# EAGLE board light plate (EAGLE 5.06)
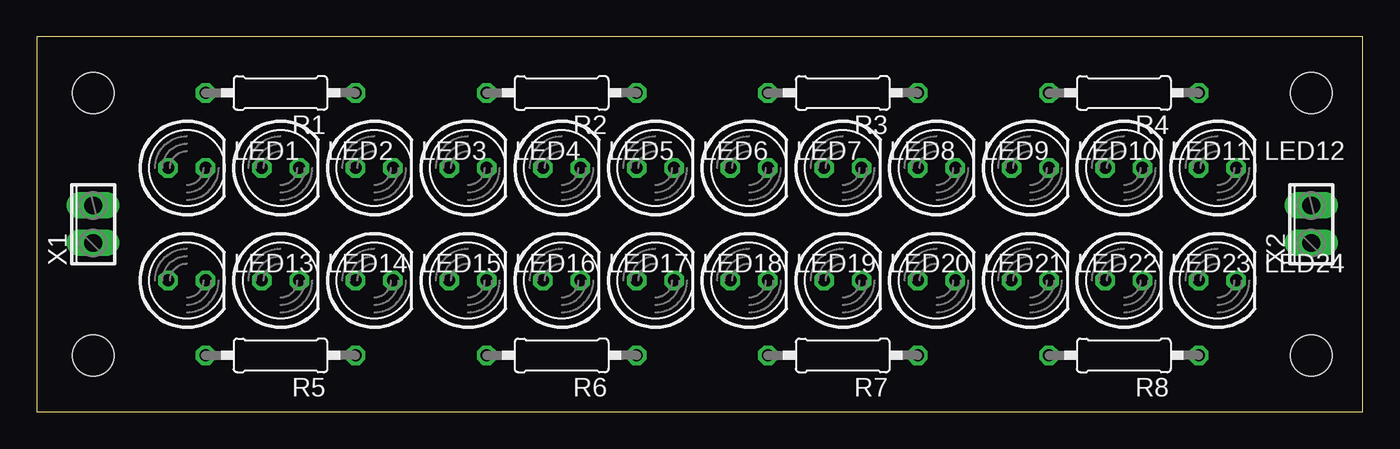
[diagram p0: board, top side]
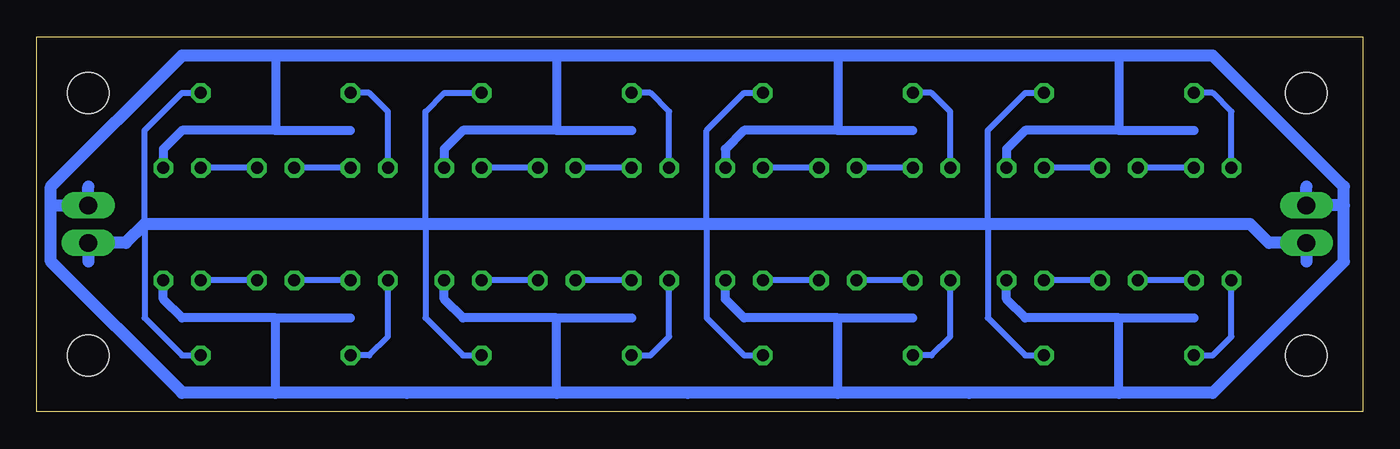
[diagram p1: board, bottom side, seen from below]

Size 89.84 x 25.39 mm. Coordinates in mm from the lower left corner, seen from the top.
Outline: 0,0 89.84,0 89.84,25.39 0,25.39 0,0
Copper layers (1*16): Top 0.035mm / dielectric 1.5mm / Bottom 0.035mm
Design rules "default": minimum track width 10mil, minimum drill 24mil, track to track 8mil, track to pad 8mil, pad to pad 8mil, via to via 8mil, smd to smd 8mil, copper to edge 40mil, drill to drill 8mil, minimum pad ring 10mil, minimum via ring 8mil, stop-mask expansion 4mil, vias tented up to drill 0mil, thermal gap 10mil
Holes 2.8 mm at 3.81,21.59 3.81,3.81 86.36,21.59 86.36,3.81

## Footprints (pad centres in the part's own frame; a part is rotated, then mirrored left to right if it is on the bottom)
LED5MM = drill 0.813 octagon: A -1.27,0; K 1.27,0
0207/10 = drill 0.813 octagon: 1 -5.08,0; 2 5.08,0
2POL254 = drill 1.2 long: 1 -1.27,0; 2 1.27,0

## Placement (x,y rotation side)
LED1  [LED5MM]  10.16,16.51 0 top
LED2  [LED5MM]  16.51,16.51 0 top
LED3  [LED5MM]  22.86,16.51 0 top
LED4  [LED5MM]  29.21,16.51 0 top
LED5  [LED5MM]  35.56,16.51 0 top
LED6  [LED5MM]  41.91,16.51 0 top
LED7  [LED5MM]  48.26,16.51 0 top
LED8  [LED5MM]  54.61,16.51 0 top
LED9  [LED5MM]  60.96,16.51 0 top
LED10  [LED5MM]  67.31,16.51 0 top
LED11  [LED5MM]  73.66,16.51 0 top
LED12  [LED5MM]  80.01,16.51 0 top
LED13  [LED5MM]  10.16,8.89 0 top
LED14  [LED5MM]  16.51,8.89 0 top
LED15  [LED5MM]  22.86,8.89 0 top
LED16  [LED5MM]  29.21,8.89 0 top
LED17  [LED5MM]  35.56,8.89 0 top
LED18  [LED5MM]  41.91,8.89 0 top
LED19  [LED5MM]  48.26,8.89 0 top
LED20  [LED5MM]  54.61,8.89 0 top
LED21  [LED5MM]  60.96,8.89 0 top
LED22  [LED5MM]  67.31,8.89 0 top
LED23  [LED5MM]  73.66,8.89 0 top
LED24  [LED5MM]  80.01,8.89 0 top
R1  [0207/10]  16.51,21.59 180 top
R2  [0207/10]  35.56,21.59 180 top
R3  [0207/10]  54.61,21.59 180 top
R4  [0207/10]  73.66,21.59 180 top
R5  [0207/10]  16.51,3.81 180 top
R6  [0207/10]  35.56,3.81 180 top
R7  [0207/10]  54.61,3.81 180 top
R8  [0207/10]  73.66,3.81 180 top
X1  [2POL254]  3.81,12.7 90 top
X2  [2POL254]  86.36,12.7 90 top

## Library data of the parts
LED1-LED24 = led
R1-R8 = rcl
X1 X2 = con-phoenix-254

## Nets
GND: LED3.K LED6.K LED9.K LED12.K LED15.K LED18.K LED21.K LED24.K X1.2 X2.2
N$1: LED1.K LED2.A
N$2: LED2.K LED3.A
N$3: LED4.K LED5.A
N$4: LED5.K LED6.A
N$5: LED7.K LED8.A
N$6: LED8.K LED9.A
N$7: LED10.K LED11.A
N$8: LED11.K LED12.A
N$9: LED13.K LED14.A
N$10: LED14.K LED15.A
N$11: LED16.K LED17.A
N$12: LED17.K LED18.A
N$13: LED19.K LED20.A
N$14: LED20.K LED21.A
N$15: LED22.K LED23.A
N$16: LED23.K LED24.A
N$17: LED1.A R1.2
N$18: LED4.A R2.2
N$19: LED7.A R3.2
N$20: LED10.A R4.2
N$21: LED13.A R5.2
N$22: LED16.A R6.2
N$23: LED19.A R7.2
N$24: LED22.A R8.2
N$25: R1.1 R2.1 R3.1 R4.1 R5.1 R6.1 R7.1 R8.1 X1.1 X2.1

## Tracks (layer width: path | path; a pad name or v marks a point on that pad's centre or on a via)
GND
  Bottom 0.61: LED12.K 81.28,17.78 80.01,19.05 73.66,19.05 | LED9.K 62.23,17.78 60.96,19.05 54.61,19.05 | LED6.K 43.18,17.78 41.91,19.05 35.56,19.05 | LED3.K 24.13,17.78 22.86,19.05 16.51,19.05 | LED24.K 81.28,7.62 80.01,6.35 73.66,6.35 | LED21.K 62.23,7.62 60.96,6.35 54.61,6.35 | LED15.K 24.13,7.62 22.86,6.35 16.51,6.35 | 73.66,24.13 73.66,19.05 | 73.66,1.27 73.66,6.35 | 54.61,1.27 54.61,6.35 | LED18.K 43.18,7.62 41.91,6.35 35.56,6.35 | 35.56,1.27 35.56,6.35 | 16.51,1.27 16.51,6.35 | 16.51,24.13 16.51,19.05 | 35.56,24.13 35.56,19.05 | 35.56,6.35 30.48,6.35 | 35.56,19.05 30.48,19.05 | 16.51,19.05 11.43,19.05 | 16.51,6.35 11.43,6.35 | 54.61,24.13 54.61,19.05 | 54.61,19.05 49.53,19.05 | 73.66,19.05 68.58,19.05 | 73.66,6.35 68.58,6.35 | 54.61,6.35 49.53,6.35
  Bottom 0.813: 88.9,13.97 88.9,15.24 80.01,24.13 73.66,24.13 64.77,24.13 54.61,24.13 45.72,24.13 35.56,24.13 26.67,24.13 16.51,24.13 10.16,24.13 1.27,15.24 1.27,13.97 | 88.9,13.97 X2.2 | 88.9,13.97 88.9,10.16 80.01,1.27 73.66,1.27 64.77,1.27 54.61,1.27 45.72,1.27 35.56,1.27 26.67,1.27 16.51,1.27 10.16,1.27 1.27,10.16 1.27,13.97 | 1.27,13.97 X1.2 | X1.2 5.08,13.97 | X2.2 85.09,13.97 | X2.2 86.36,15.24 | X1.2 3.81,15.24
N$1
  Bottom 0.406: LED1.K LED2.A
N$2
  Bottom 0.406: LED2.K LED3.A
N$3
  Bottom 0.406: LED4.K LED5.A
N$4
  Bottom 0.406: LED5.K LED6.A
N$5
  Bottom 0.406: LED7.K LED8.A
N$6
  Bottom 0.406: LED8.K LED9.A
N$7
  Bottom 0.406: LED10.K LED11.A
N$8
  Bottom 0.406: LED11.K LED12.A
N$9
  Bottom 0.406: LED13.K LED14.A
N$10
  Bottom 0.406: LED14.K LED15.A
N$11
  Bottom 0.406: LED16.K LED17.A
N$12
  Bottom 0.406: LED17.K LED18.A
N$13
  Bottom 0.406: LED19.K LED20.A
N$14
  Bottom 0.406: LED20.K LED21.A
N$15
  Bottom 0.406: LED22.K LED23.A
N$16
  Bottom 0.406: LED23.K LED24.A
N$17
  Bottom 0.406: R1.2 10.16,21.59 8.89,20.32 LED1.A
N$18
  Bottom 0.406: R2.2 29.21,21.59 27.94,20.32 LED4.A
N$19
  Bottom 0.406: R3.2 48.26,21.59 46.99,20.32 LED7.A
N$20
  Bottom 0.406: R4.2 67.31,21.59 66.04,20.32 LED10.A
N$21
  Bottom 0.406: R5.2 10.16,3.81 8.89,5.08 LED13.A
N$22
  Bottom 0.406: R6.2 29.21,3.81 27.94,5.08 LED16.A
N$23
  Bottom 0.406: R7.2 48.26,3.81 46.99,5.08 LED19.A
N$24
  Bottom 0.406: R8.2 67.31,3.81 66.04,5.08 LED22.A
N$25
  Bottom 0.406: R1.1 22.86,21.59 25.4,19.05 25.4,12.7 25.4,6.35 22.86,3.81 R5.1 | R6.1 41.91,3.81 44.45,6.35 44.45,12.7 44.45,19.05 41.91,21.59 R2.1 | R7.1 60.96,3.81 63.5,6.35 63.5,12.7 63.5,20.32 62.23,21.59 R3.1 | R8.1 80.01,3.81 82.55,6.35 82.55,12.7 82.55,19.05 80.01,21.59 R4.1
  Bottom 0.813: X1.1 6.35,11.43 7.62,12.7 25.4,12.7 44.45,12.7 63.5,12.7 82.55,12.7 83.82,11.43 X2.1 | X2.1 86.36,10.16 | X1.1 3.81,10.16 | X1.1 2.54,11.43 | X2.1 87.63,11.43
